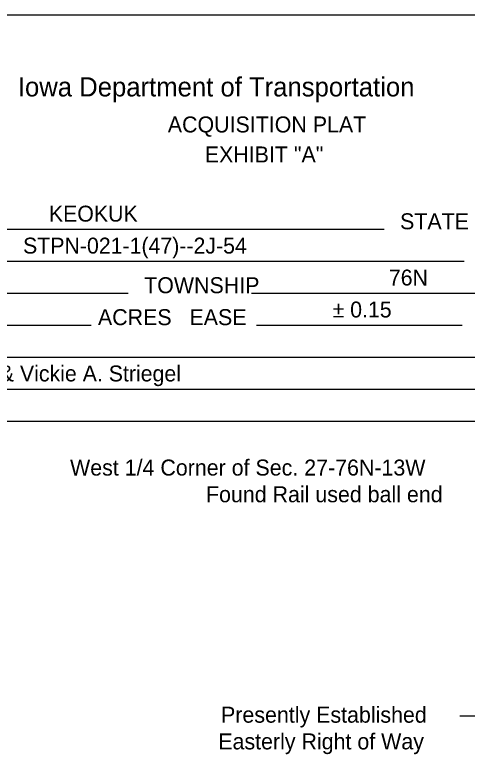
# Model space of a CAD drawing. Extents: x 23379288 to 23380138, y 6801100 to 6802500.
# Drawn here: x 23379532.6 to 23379815.5, y 6802037.8 to 6802500.5 of the extents above; entities that cross this region are included whole.
import ezdxf

# ---------------------------------------------------------------- set-up
doc = ezdxf.new("R2010")
doc.units = 0
for name, color, linetype in [('DisPlatCells', 7, 'Continuous'), ('DisPlatData', 7, 'Continuous'), ('Kevin', 7, 'Continuous'), ('Kevin_Text', 7, 'Continuous'), ('Level 60', 7, 'Continuous')]:
    doc.layers.add(name, color=color, linetype=linetype)

msp = doc.modelspace()

# ---------------------------------------------------------------- linework, layer by layer
at = {"layer": 'DisPlatCells'}
for p, q in [((23379379.82, 6802366.26), (23379763.49, 6802366.26)), ((23379420.76, 6802346.26), (23379813.49, 6802346.26)), ((23379390.56, 6802326.27), (23379603.49, 6802326.27)), ((23379680.68, 6802326.27), (23379863.49, 6802326.27)), ((23379390.56, 6802306.27), (23379580.39, 6802306.27)), ((23379683.79, 6802306.27), (23379812.4, 6802306.27)), ((23379439.22, 6802286.27), (23380063.5, 6802286.27)), ((23379439.22, 6802266.26), (23380063.5, 6802266.26)), ((23379328.47, 6802246.26), (23380063.5, 6802246.26))]:
    msp.add_line(p, q, dxfattribs=at)
at = {"layer": 'Kevin'}
msp.add_line((23379890.44, 6802061.6), (23379810.9, 6802061.51), dxfattribs=at)
at = {"layer": 'Level 60'}
msp.add_line((23379287.77, 6802500.47), (23380137.79, 6802500.47), dxfattribs=at)

# ---------------------------------------------------------------- texts
at = {"layer": 'DisPlatCells'}
for s, height, p in [('Iowa Department of Transportation', 12.0002, (23379534.52, 6802449.38)), ('ACQUISITION PLAT', 10.0002, (23379628.26, 6802426.84)), ('EXHIBIT "A"', 10.0002, (23379651.39, 6802408.08)), ('STATE CONTROL NO.', 10.0002, (23379773.48, 6802366.26)), ('TOWNSHIP', 10, (23379613.49, 6802326.27)), ('ACRES   EASE', 10.0002, (23379584.59, 6802306.27))]:
    msp.add_text(s, height=height, dxfattribs=at).set_placement(p)
at = {"layer": 'DisPlatData'}
for s, height, p in [('KEOKUK', 9.96, (23379553.92, 6802371.06)), ('STPN-021-1(47)--2J-54', 9.9602, (23379537.78, 6802351.06)), ('76N', 9.96, (23379766.47, 6802331.07)), ('%%P 0.15', 9.96, (23379731.29, 6802311.07)), ('James L. & Vickie A. Striegel', 9.9602, (23379465.51, 6802271.06))]:
    msp.add_text(s, height=height, dxfattribs=at).set_placement(p)
at = {"layer": 'Kevin_Text'}
for s, p in [('West 1/4 Corner of Sec. 27-76N-13W', (23379567.15, 6802212.16)), ('Found Rail used ball end', (23379652.14, 6802195.46)), ('Presently Established', (23379661.56, 6802057.52)), ('Easterly Right of Way', (23379659.83, 6802040.82))]:
    msp.add_text(s, height=10.0002, dxfattribs=at).set_placement(p)

doc.saveas('drawing.dxf')
